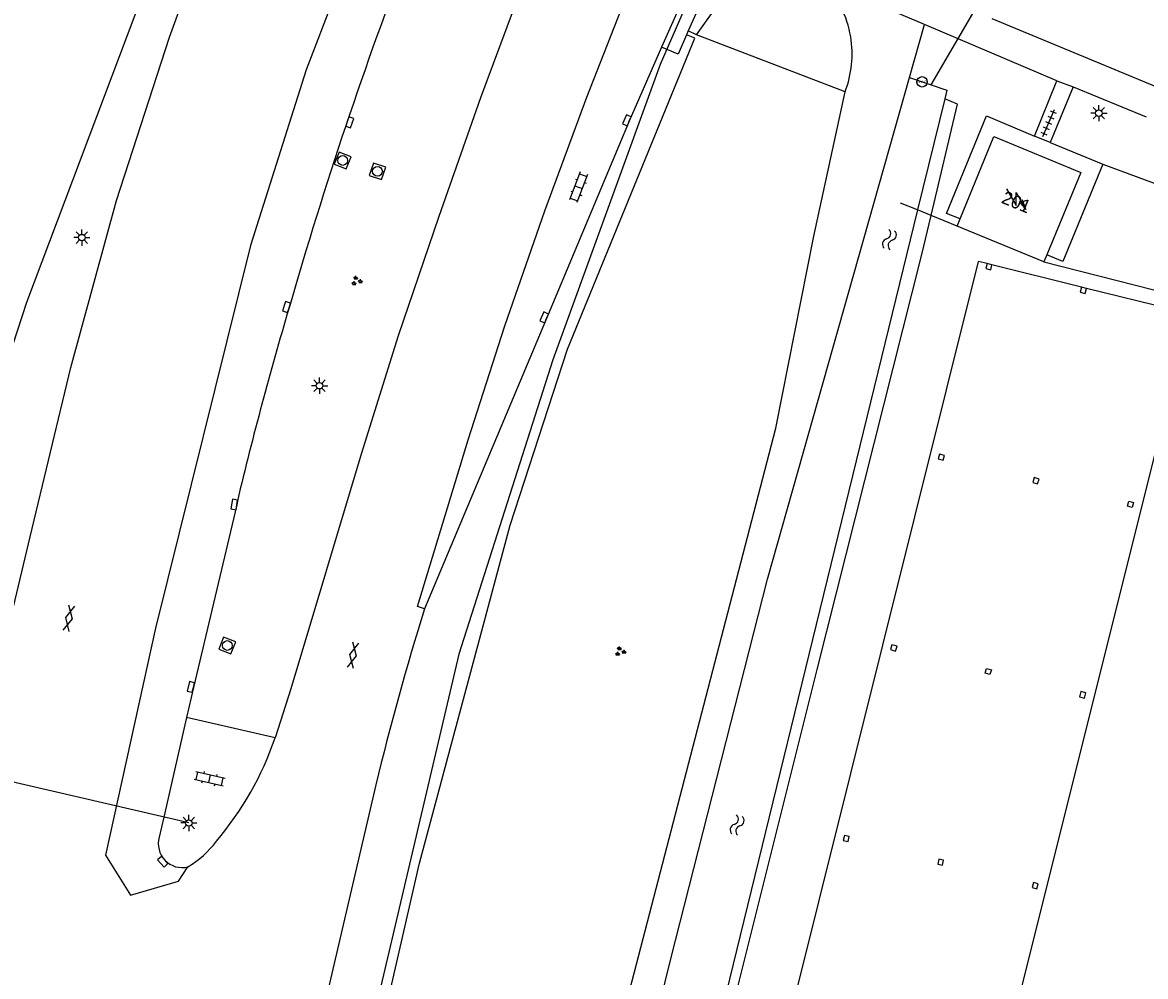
# Model space of a CAD drawing. Extents: x 131000 to 133013, y 393000 to 396501.
# Drawn here: x 131491.8 to 131578.2, y 394722.3 to 394795.7 of the extents above; entities that cross this region are included whole.
import ezdxf

# ---------------------------------------------------------------- set-up
doc = ezdxf.new("R2010")
doc.units = 0
for name, color, linetype in [('gg-afsc-hekwerk', 7, 'Continuous'), ('gg-anno-huisnummerreeks BGT', 7, 'Continuous'), ('gg-bbg-hoofdgebouw', 7, 'Continuous'), ('gg-bbg-luifel en loopbrug', 7, 'Continuous'), ('gg-bbg-pilaar overkapping', 7, 'Continuous'), ('gg-knt-bovenkant onderkant talud', 7, 'Continuous'), ('gg-knt-verharding', 7, 'Continuous'), ('gg-kntw-bovenkant insteek waterloop', 7, 'Continuous'), ('gg-kwrk-duiker nz buis', 7, 'Continuous'), ('gg-kwrk-kunstwerk', 7, 'Continuous'), ('gt-grn-groengrens', 7, 'Continuous'), ('gt-grn-vlakafsluiter', 7, 'Continuous'), ('gt-grn-weggrens', 7, 'Continuous'), ('gt-knt-geleideconstructie', 7, 'Continuous'), ('gt-knt-lijn portaal', 7, 'Continuous'), ('gt-symb-gesloten verharding', 7, 'Continuous'), ('gt-symb-groenvak', 7, 'Continuous'), ('gt-symb-hoogtemerk', 7, 'Continuous'), ('gt-symb-klinker verharding', 7, 'Continuous'), ('gt-symb-kolk', 7, 'Continuous'), ('gt-symb-lichtmast', 7, 'Continuous'), ('gt-symb-rioolschacht', 7, 'Continuous'), ('gt-symb-tegel verharding', 7, 'Continuous'), ('gt-symb-trafo symbool', 7, 'Continuous'), ('gt-symb-watersymbool', 7, 'Continuous')]:
    doc.layers.add(name, color=color, linetype=linetype)

# ---------------------------------------------------------------- blocks, each defined once
blk = doc.blocks.new('gt0-HMERK')
at = {"layer": 'gt-symb-hoogtemerk'}
blk.add_circle((0, 0), 0.4, dxfattribs=at)
blk.add_text('N.A.P', height=0.2, dxfattribs=at).set_placement((-0.354, -0.1))
blk = doc.blocks.new('gt0-RS')
at = {"layer": 'gt-symb-rioolschacht'}
blk.add_lwpolyline([(-0.5, -0.5), (0.5, -0.5), (0.5, 0.5), (-0.5, 0.5)], close=True, dxfattribs=at)
blk.add_circle((0, 0), 0.375, dxfattribs=at)
blk = doc.blocks.new('gt0-KOLK')
at = {"layer": 'gt-symb-kolk'}
blk.add_lwpolyline([(0, 0), (0.375, 0), (0.375, 0.4), (-0.375, 0.4), (-0.375, 0), (0, 0)], dxfattribs=at)
blk = doc.blocks.new('gt0-KL1')
at = {"layer": 'gt-symb-klinker verharding'}
for p, q in [((-1.15, 0.3), (1.15, 0.3)), ((-1, -0.3), (-1, 0.3)), ((-0.5, 0.3), (-0.5, 0.45)), ((0, -0.3), (0, 0.3)), ((0.5, 0.3), (0.5, 0.45)), ((1, -0.3), (1, 0.3)), ((-1.15, -0.3), (1.15, -0.3)), ((-0.5, -0.45), (-0.5, -0.3)), ((0.5, -0.45), (0.5, -0.3))]:
    blk.add_line(p, q, dxfattribs=at)
blk = doc.blocks.new('gt0-LMAST')
at = {"layer": 'gt-symb-lichtmast'}
for p, q in [((-0.182, 0.173), (-0.447, 0.438)), ((-0.005, 0.246), (-0.005, 0.621)), ((0.172, 0.173), (0.437, 0.438)), ((-0.255, -0.004), (-0.63, -0.004)), ((-0.182, -0.181), (-0.447, -0.446)), ((-0.005, -0.254), (-0.005, -0.629)), ((0.437, -0.446), (0.172, -0.181)), ((0.245, -0.004), (0.62, -0.004))]:
    blk.add_line(p, q, dxfattribs=at)
blk.add_circle((-0.005, -0.004), 0.25, dxfattribs=at)
blk = doc.blocks.new('gt0-HSP')
at = {"layer": 'gt-symb-trafo symbool'}
for points in [[(0.771, 0.746), (-0.529, -0.004), (0.471, -0.004), (-0.829, -0.754)], [(-0.217, -0.24), (-0.829, -0.754), (-0.077, -0.48)]]:
    blk.add_lwpolyline(points, dxfattribs=at)
blk = doc.blocks.new('gt0-TEG1')
at = {"layer": 'gt-symb-tegel verharding'}
for p, q in [((-1.125, 0), (1.125, 0)), ((-0.9, -0.25), (-0.9, 0.25)), ((-0.45, -0.25), (-0.45, 0.25)), ((0, -0.25), (0, 0.25)), ((0.45, -0.25), (0.45, 0.25)), ((0.9, -0.25), (0.9, 0.25))]:
    blk.add_line(p, q, dxfattribs=at)
blk = doc.blocks.new('gt0-GESVH1')
at = {"layer": 'gt-symb-gesloten verharding'}
for p, q in [((-0.992, -0.261), (0.008, 0.239)), ((0.008, -0.261), (-0.992, 0.239)), ((0.008, 0.239), (1.008, -0.261)), ((1.008, 0.239), (0.008, -0.261))]:
    blk.add_line(p, q, dxfattribs=at)
blk = doc.blocks.new('gt0-WA')
at = {"layer": 'gt-symb-watersymbool'}
for centre, start, end in [((-0.323, 0.022), 28.07249, 151.92751), ((0.427, 0.422), 208.07248, 331.92751), ((-0.323, -0.428), 28.07249, 151.92751), ((0.427, -0.028), 208.07248, 331.92751)]:
    blk.add_arc(centre, 0.425, start, end, dxfattribs=at)
blk = doc.blocks.new('gt0-GRVAK')
at = {"layer": 'gt-symb-groenvak'}
for p, q in [((-0.11, 0.189), (-0.228, 0.24)), ((-0.182, 0.153), (0.088, 0.153)), ((-0.091, 0.211), (-0.156, 0.322)), ((-0.047, 0.214), (-0.047, 0.393)), ((-0.004, 0.211), (0.061, 0.322)), ((0.015, 0.189), (0.133, 0.24)), ((0.262, -0.052), (0.197, 0.059)), ((0.305, -0.049), (0.305, 0.13)), ((0.349, -0.052), (0.414, 0.059)), ((-0.245, -0.228), (-0.363, -0.177)), ((-0.318, -0.264), (-0.047, -0.264)), ((-0.226, -0.206), (-0.291, -0.095)), ((-0.183, -0.203), (-0.183, -0.024)), ((-0.139, -0.206), (-0.074, -0.095)), ((-0.12, -0.228), (-0.002, -0.177)), ((0.243, -0.074), (0.125, -0.023)), ((0.17, -0.11), (0.441, -0.11)), ((0.368, -0.074), (0.486, -0.023))]:
    blk.add_line(p, q, dxfattribs=at)

msp = doc.modelspace()

# ---------------------------------------------------------------- linework, layer by layer
at = {"layer": 'gg-afsc-hekwerk'}
for p, q in [((131560.671, 394781.244), (131559.371, 394781.778)), ((131561.715, 394780.815), (131560.671, 394781.244)), ((131563.718, 394779.992), (131561.715, 394780.815)), ((131570.392, 394777.25), (131585.343, 394773.453))]:
    msp.add_line(p, q, dxfattribs=at)
at = {"layer": 'gg-bbg-hoofdgebouw'}
for p, q in [((131563.718, 394779.992), (131563.954, 394780.568)), ((131570.392, 394777.25), (131563.718, 394779.992)), ((131570.626, 394777.802), (131570.392, 394777.25))]:
    msp.add_line(p, q, dxfattribs=at)
msp.add_lwpolyline([(131563.954, 394780.568), (131566.552, 394786.889), (131573.228, 394784.137), (131570.626, 394777.802)], dxfattribs=at)
at = {"layer": 'gg-bbg-luifel en loopbrug'}
for p, q in [((131566.398, 394777.026), (131566.022, 394777.12)), ((131573.285, 394775.312), (131566.398, 394777.026)), ((131573.668, 394775.217), (131573.285, 394775.312)), ((131580.554, 394773.503), (131573.668, 394775.217)), ((131567.175, 394715.452), (131581.322, 394772.031))]:
    msp.add_line(p, q, dxfattribs=at)
msp.add_lwpolyline([(131566.022, 394777.12), (131565.345, 394777.288), (131550.607, 394718.271), (131551.276, 394718.102)], dxfattribs=at)
at = {"layer": 'gg-bbg-pilaar overkapping'}
for points in [[(131566.022, 394777.12), (131565.931, 394776.744), (131566.306, 394776.653), (131566.398, 394777.026)], [(131573.285, 394775.312), (131573.189, 394774.931), (131573.572, 394774.834), (131573.668, 394775.217)], [(131562.256, 394762.101), (131562.632, 394761.997), (131562.734, 394762.364), (131562.359, 394762.469), (131562.256, 394762.101)], [(131569.534, 394760.29), (131569.911, 394760.182), (131570.016, 394760.55), (131569.639, 394760.657), (131569.534, 394760.29)], [(131577.289, 394758.738), (131577.182, 394758.354), (131576.811, 394758.458), (131576.917, 394758.841), (131577.289, 394758.738)], [(131558.599, 394747.435), (131558.985, 394747.323), (131559.09, 394747.685), (131558.705, 394747.798), (131558.599, 394747.435)], [(131566.35, 394745.868), (131566.24, 394745.514), (131565.864, 394745.63), (131565.974, 394745.985), (131566.35, 394745.868)], [(131573.141, 394743.802), (131573.524, 394743.708), (131573.622, 394744.107), (131573.238, 394744.201), (131573.141, 394743.802)], [(131554.949, 394732.754), (131555.324, 394732.665), (131555.416, 394733.049), (131555.04, 394733.138), (131554.949, 394732.754)], [(131562.22, 394730.929), (131562.586, 394730.846), (131562.677, 394731.239), (131562.31, 394731.323), (131562.22, 394730.929)], [(131569.488, 394729.126), (131569.857, 394729.028), (131569.962, 394729.422), (131569.592, 394729.52), (131569.488, 394729.126)]]:
    msp.add_lwpolyline(points, dxfattribs=at)
at = {"layer": 'gg-knt-bovenkant onderkant talud'}
msp.add_line((131552.691, 394779.223), (131555.094, 394790.336), dxfattribs=at)
for centre, radius, start, end in [((131547.515, 394793.245), 8.119, 9.38419, 43.32422), ((131547.516, 394793.248), 8.118, 338.97955, 9.36613)]:
    msp.add_arc(centre, radius, start, end, dxfattribs=at)
at = {"layer": 'gg-knt-verharding'}
for p, q in [((131543.652, 394794.71), (131548.389, 394801.314)), ((131561.212, 394795.503), (131553.422, 394798.816)), ((131542.473, 394797.158), (131540.984, 394793.758)), ((131571.398, 394791.17), (131561.212, 394795.503)), ((131579.023, 394790.706), (131566.406, 394795.948)), ((131543.652, 394794.71), (131543.033, 394795.031)), ((131569.662, 394786.922), (131571.398, 394791.17)), ((131572.635, 394790.718), (131570.871, 394786.432)), ((131572.635, 394790.718), (131578.258, 394788.398)), ((131570.871, 394786.432), (131574.924, 394784.78)), ((131504.428, 394742.201), (131502.679, 394734.544)), ((131511.244, 394740.644), (131504.428, 394742.201)), ((131502.679, 394734.544), (131502.327, 394733.005))]:
    msp.add_line(p, q, dxfattribs=at)
for points in [[(131489.286, 394743.192), (131492.407, 394756.105), (131495.515, 394769.125), (131499.052, 394781.981), (131503.125, 394794.542), (131507.853, 394807.61), (131505.773, 394808.653), (131505.811, 394808.726)], [(131531.487, 394801.846), (131530.051, 394797.935), (131527.054, 394789.866), (131523.828, 394780.739), (131520.724, 394771.559), (131517.863, 394762.475), (131512.449, 394744.409), (131511.244, 394740.644)], [(131522.733, 394750.567), (131522.208, 394750.758), (131526.098, 394763.561), (131528.922, 394772.337), (131531.996, 394781.185), (131535.224, 394789.921), (131538.701, 394798.772)], [(131512.312, 394687.172), (131522.35, 394731.01), (131529.33, 394757.01), (131533.73, 394770.55), (131543.54, 394794.45), (131542.894, 394794.712)], [(131540.984, 394793.758), (131538.493, 394788.068), (131532.132, 394772.898), (131522.733, 394750.567)], [(131563.954, 394780.568), (131562.894, 394780.984), (131565.966, 394788.498), (131569.662, 394786.922)], [(131574.924, 394784.78), (131571.843, 394777.29), (131570.626, 394777.802)], [(131508.34, 394758.858), (131508.297, 394758.565), (131504.957, 394744.515), (131504.428, 394742.201)], [(131518.988, 394737.023), (131513.993, 394715.59), (131513.47, 394715.698), (131509.555, 394698.614), (131507.256, 394688.19)]]:
    msp.add_lwpolyline(points, dxfattribs=at)
for centre, radius, start, end in [((131845.324, 394677.517), 346.624, 159.04307, 163.88663), ((131787.816, 394692.029), 287.356, 163.48408, 166.55185), ((131753.746, 394679.401), 241.727, 162.87794, 166.20916), ((131488.12, 394748.523), 24.429, 319.60366, 341.18472), ((131504.089, 394732.501), 1.833, 164.0551, 284.2621), ((131500.396, 394737.526), 7.965, 301.36272, 322.6233)]:
    msp.add_arc(centre, radius, start, end, dxfattribs=at)
at = {"layer": 'gg-kntw-bovenkant insteek waterloop'}
msp.add_line((131562.763, 394789.804), (131560.671, 394781.244), dxfattribs=at)
for points in [[(131531.92, 394683.719), (131537.325, 394705.961), (131541.678, 394723.642), (131549.137, 394752.842), (131560.058, 394791.427)], [(131560.058, 394791.427), (131562.921, 394790.449), (131562.763, 394789.804)], [(131560.671, 394781.244), (131540.642, 394699.314), (131536.212, 394682.822)]]:
    msp.add_lwpolyline(points, dxfattribs=at)
at = {"layer": 'gg-kwrk-duiker nz buis'}
msp.add_line((131576.816, 394816.757), (131561.688, 394790.87), dxfattribs=at)
at = {"layer": 'gg-kwrk-kunstwerk'}
for p, q in [((131543.729, 394796.621), (131543.033, 394795.031)), ((131543.033, 394795.031), (131542.894, 394794.712))]:
    msp.add_line(p, q, dxfattribs=at)
msp.add_lwpolyline([(131542.894, 394794.712), (131542.248, 394793.236), (131540.984, 394793.758)], dxfattribs=at)
at = {"layer": 'gt-grn-groengrens'}
for p, q in [((131560.058, 394791.427), (131561.212, 394795.503)), ((131555.094, 394790.336), (131543.652, 394794.71))]:
    msp.add_line(p, q, dxfattribs=at)
for points in [[(131561.715, 394780.815), (131563.756, 394789.389), (131562.763, 394789.804)], [(131574.924, 394784.78), (131581.443, 394782.362), (131583.406, 394778.756), (131583.699, 394777.641), (131585.701, 394774.861), (131585.343, 394773.453)], [(131536.073, 394682.25), (131536.954, 394682.029), (131537.805, 394686.259), (131538.923, 394686.381), (131538.826, 394689.395), (131542.808, 394705.4), (131552.96, 394745.89), (131561.001, 394777.818), (131561.715, 394780.815)], [(131528.78, 394683.677), (131531.842, 394695.513), (131549.767, 394764.458), (131552.691, 394779.223)]]:
    msp.add_lwpolyline(points, dxfattribs=at)
at = {"layer": 'gt-grn-vlakafsluiter'}
msp.add_line((131571.398, 394791.17), (131572.635, 394790.718), dxfattribs=at)
at = {"layer": 'gt-grn-weggrens'}
msp.add_line((131570.871, 394786.432), (131569.662, 394786.922), dxfattribs=at)
msp.add_lwpolyline([(131519.515, 394806.984), (131517.88, 394803.124), (131513.642, 394792.032), (131509.345, 394778.523), (131502.031, 394749.072), (131498.187, 394731.624), (131500.121, 394728.547), (131503.818, 394729.62), (131504.541, 394730.725)], dxfattribs=at)
at = {"layer": 'gt-knt-geleideconstructie'}
for points in [[(131481.905, 394743.848), (131484.688, 394751.3), (131492.146, 394774.165), (131501.075, 394797.85), (131505.105, 394807.858), (131522.547, 394843.816), (131530.116, 394857.718)], [(131557.139, 394829.717), (131540.868, 394792.432), (131532.614, 394769.717), (131525.39, 394747.09), (131514.394, 394700.364)]]:
    msp.add_lwpolyline(points, dxfattribs=at)
at = {"layer": 'gt-knt-lijn portaal'}
msp.add_line((131504.605, 394734.097), (131485.385, 394738.558), dxfattribs=at)

# ---------------------------------------------------------------- block references
at = {"layer": 'gt-symb-gesloten verharding'}
for p, rotation in [((131495.387, 394749.854), -102.29885517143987), ((131517.245, 394747.003), -102.2988551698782)]:
    msp.add_blockref('gt0-GESVH1', p, dxfattribs=dict(at, rotation=rotation))
at = {"layer": 'gt-symb-groenvak'}
for p in [(131517.506, 394775.785), (131537.784, 394747.287)]:
    msp.add_blockref('gt0-GRVAK', p, dxfattribs=at)
at = {"layer": 'gt-symb-hoogtemerk'}
msp.add_blockref('gt0-HMERK', (131561.018, 394791.099), dxfattribs=at)
at = {"layer": 'gt-symb-klinker verharding'}
for p, rotation in [((131534.588, 394782.996), -110.55604521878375), ((131506.201, 394737.504), -12.827123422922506)]:
    msp.add_blockref('gt0-KL1', p, dxfattribs=dict(at, rotation=rotation))
at = {"layer": 'gt-symb-kolk'}
for p, rotation in [((131538.493, 394788.068), 67.24854356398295), ((131516.796, 394788.045), -108.57020652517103), ((131512.317, 394773.719), 71.88148643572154), ((131532.132, 394772.898), 67.17652352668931), ((131508.297, 394758.565), 81.70784571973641), ((131504.957, 394744.515), 76.62731652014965), ((131502.747, 394731.255), 132.87679162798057)]:
    msp.add_blockref('gt0-KOLK', p, dxfattribs=dict(at, rotation=rotation))
at = {"layer": 'gt-symb-lichtmast'}
for p in [(131574.628, 394788.696), (131496.379, 394779.125), (131514.668, 394767.733), (131504.61, 394734.101)]:
    msp.add_blockref('gt0-LMAST', p, dxfattribs=at)
at = {"layer": 'gt-symb-rioolschacht'}
for p, rotation in [((131516.444, 394785.052), 68.17161721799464), ((131519.119, 394784.215), 71.01385277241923), ((131507.562, 394747.748), 68.12816027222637)]:
    msp.add_blockref('gt0-RS', p, dxfattribs=dict(at, rotation=rotation))
at = {"layer": 'gt-symb-tegel verharding', "rotation": 66.61335784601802}
msp.add_blockref('gt0-TEG1', (131570.768, 394787.928), dxfattribs=at)
at = {"layer": 'gt-symb-trafo symbool', "rotation": 90}
msp.add_blockref('gt0-HSP', (131568.253, 394782.106), dxfattribs=at)
at = {"layer": 'gt-symb-watersymbool'}
for p, rotation in [((131558.492, 394778.924), 76.28353067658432), ((131546.773, 394733.884), 76.28353067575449)]:
    msp.add_blockref('gt0-WA', p, dxfattribs=dict(at, rotation=rotation))

# ---------------------------------------------------------------- texts
at = {"layer": 'gg-anno-huisnummerreeks BGT'}
msp.add_text('201', height=1, rotation=337.6, dxfattribs=at).set_placement((131567.053, 394781.815))

doc.saveas('drawing.dxf')
